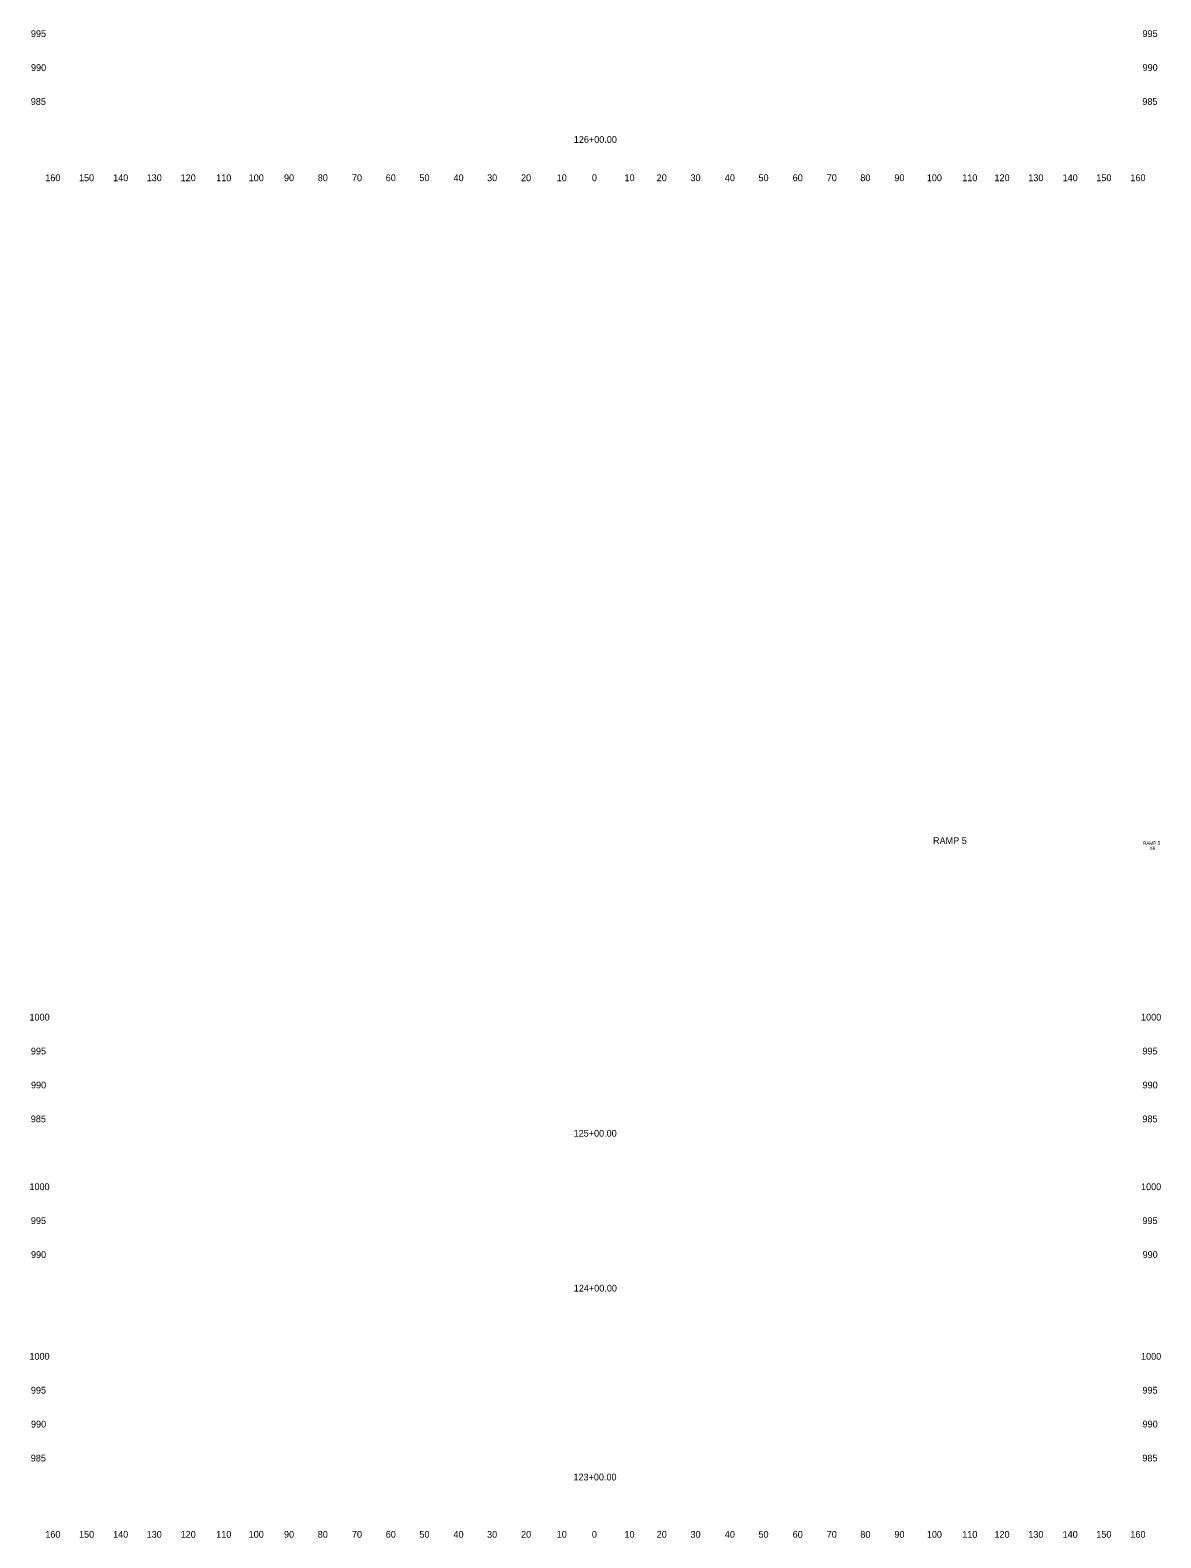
# Model space of a CAD drawing. Extents: x 4994 to 5842, y 4997 to 8804.
# Drawn here: x 4993.6 to 5327.1, y 6997.5 to 7442 of the extents above; entities that cross this region are included whole.
import ezdxf

# ---------------------------------------------------------------- set-up
doc = ezdxf.new("R2010")
doc.units = 0
for name, color, linetype in [('CLS_Search_Dist', 7, 'Continuous'), ('RD_XE_Ground', 7, 'Continuous'), ('UC_PD_Text', 7, 'Continuous')]:
    doc.layers.add(name, color=color, linetype=linetype)

msp = doc.modelspace()

# ---------------------------------------------------------------- texts
at = {"layer": 'CLS_Search_Dist'}
for s, p in [('995', (4993.86, 7440)), ('995', (5321.66, 7440)), ('990', (4993.89, 7430)), ('990', (5321.69, 7430)), ('985', (4993.83, 7420)), ('985', (5321.63, 7420)), ('160', (4998.1, 7397.5)), ('150', (5008.04, 7397.5)), ('140', (5018.1, 7397.5)), ('130', (5027.99, 7397.5)), ('120', (5038.01, 7397.5)), ('110', (5048.51, 7397.5)), ('100', (5058.07, 7397.5)), ('90', (5068.5, 7397.5)), ('80', (5078.46, 7397.5)), ('70', (5088.54, 7397.5)), ('60', (5098.5, 7397.5)), ('50', (5108.43, 7397.5)), ('40', (5118.5, 7397.5)), ('30', (5128.39, 7397.5)), ('20', (5138.4, 7397.5)), ('10', (5148.91, 7397.5)), ('0', (5159.3, 7397.5)), ('0', (5159.3, 7397.5)), ('10', (5168.91, 7397.5)), ('20', (5178.4, 7397.5)), ('30', (5188.39, 7397.5)), ('40', (5198.5, 7397.5)), ('50', (5208.43, 7397.5)), ('60', (5218.5, 7397.5)), ('70', (5228.54, 7397.5)), ('80', (5238.46, 7397.5)), ('90', (5248.5, 7397.5)), ('100', (5258.07, 7397.5)), ('110', (5268.51, 7397.5)), ('120', (5278.01, 7397.5)), ('130', (5287.99, 7397.5)), ('140', (5298.1, 7397.5)), ('150', (5308.04, 7397.5)), ('160', (5318.1, 7397.5)), ('1000', (4993.44, 7150)), ('1000', (5321.24, 7150)), ('995', (4993.86, 7140)), ('995', (5321.66, 7140)), ('990', (4993.89, 7130)), ('990', (5321.69, 7130)), ('985', (4993.83, 7120)), ('985', (5321.63, 7120)), ('1000', (4993.44, 7100)), ('1000', (5321.24, 7100)), ('995', (4993.86, 7090)), ('995', (5321.66, 7090)), ('990', (4993.89, 7080)), ('990', (5321.69, 7080)), ('1000', (4993.44, 7050)), ('1000', (5321.24, 7050)), ('995', (4993.86, 7040)), ('995', (5321.66, 7040)), ('990', (4993.89, 7030)), ('990', (5321.69, 7030)), ('985', (4993.83, 7020)), ('985', (5321.63, 7020)), ('160', (4998.1, 6997.5)), ('150', (5008.04, 6997.5)), ('140', (5018.1, 6997.5)), ('130', (5027.99, 6997.5)), ('120', (5038.01, 6997.5)), ('110', (5048.51, 6997.5)), ('100', (5058.07, 6997.5)), ('90', (5068.5, 6997.5)), ('80', (5078.46, 6997.5)), ('70', (5088.54, 6997.5)), ('60', (5098.5, 6997.5)), ('50', (5108.43, 6997.5)), ('40', (5118.5, 6997.5)), ('30', (5128.39, 6997.5)), ('20', (5138.4, 6997.5)), ('10', (5148.91, 6997.5)), ('0', (5159.3, 6997.5)), ('0', (5159.3, 6997.5)), ('10', (5168.91, 6997.5)), ('20', (5178.4, 6997.5)), ('30', (5188.39, 6997.5)), ('40', (5198.5, 6997.5)), ('50', (5208.43, 6997.5)), ('60', (5218.5, 6997.5)), ('70', (5228.54, 6997.5)), ('80', (5238.46, 6997.5)), ('90', (5248.5, 6997.5)), ('100', (5258.07, 6997.5)), ('110', (5268.51, 6997.5)), ('120', (5278.01, 6997.5)), ('130', (5287.99, 6997.5)), ('140', (5298.1, 6997.5)), ('150', (5308.04, 6997.5)), ('160', (5318.1, 6997.5))]:
    msp.add_text(s, height=2, dxfattribs=at).set_placement(p)
at = {"layer": 'RD_XE_Ground'}
for s, p in [('126+00.00', (5153.96, 7408.79)), ('125+00.00', (5153.9, 7115.76)), ('124+00.00', (5153.96, 7070.09)), ('123+00.00', (5153.85, 7014.39))]:
    msp.add_text(s, height=2, dxfattribs=at).set_placement(p)
at = {"layer": 'UC_PD_Text'}
for s, height, p in [('RAMP 5', 2, (5259.89, 7202.06)), ('RAMP 5', 1, (5321.78, 7201.8)), ('X6', 1, (5323.71, 7200.3))]:
    msp.add_text(s, height=height, dxfattribs=at).set_placement(p)

doc.saveas('drawing.dxf')
